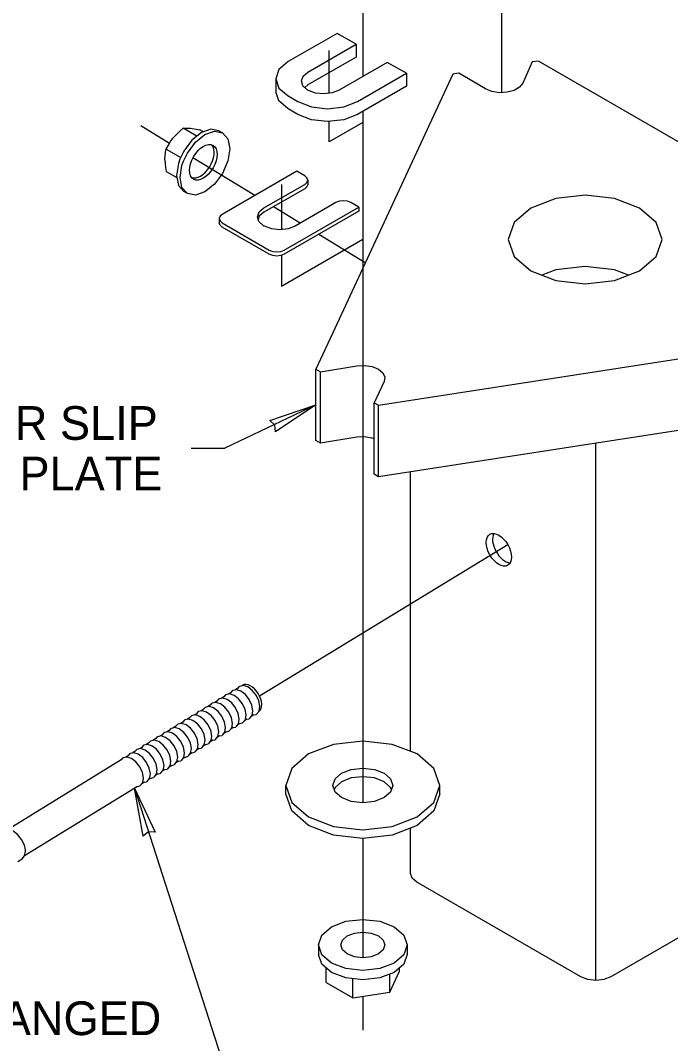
# Model space of a CAD drawing. Extents: x 99862 to 103151, y 99997 to 117076.
# Drawn here: x 100046.3 to 100354.6, y 103271 to 103756.6 of the extents above; entities that cross this region are included whole.
import ezdxf

# ---------------------------------------------------------------- set-up
doc = ezdxf.new("R2010")
doc.units = 0
for name, color, linetype in [('Default', 7, 'Continuous'), ('Level 13', 7, 'Continuous'), ('Level 15', 7, 'Continuous'), ('Level 20', 7, 'Continuous'), ('Level 4', 7, 'Continuous'), ('Level 5', 7, 'Continuous')]:
    doc.layers.add(name, color=color, linetype=linetype)

msp = doc.modelspace()

# ---------------------------------------------------------------- linework, layer by layer
at = {"layer": 'Default'}
for p, q in [((100208.71, 103891.51), (100208.71, 103729.96)), ((100274.4, 103781.42), (100274.4, 103722.3)), ((100182.62, 103732.04), (100205.47, 103745.24)), ((100192.69, 103722), (100192.69, 103742.22)), ((100206.13, 103718.06), (100229.34, 103731.46)), ((100208.71, 103713.42), (100208.71, 103385.26)), ((100192.69, 103698.9), (100192.69, 103708.63)), ((100208.71, 103708.14), (100192.69, 103698.9)), ((100161.8, 103667.56), (100181.12, 103678.72)), ((100170.11, 103678.77), (100170.11, 103657.3)), ((100208.71, 103652.54), (100170.11, 103630.25)), ((100170.11, 103645.05), (100170.11, 103630.25)), ((100195.4, 103610.36), (100186.43, 103591.03)), ((100186.43, 103591.03), (100188.55, 103589.81)), ((100214.01, 103575.11), (100216.13, 103573.89)), ((100319.2, 103300.86), (100319.2, 103555.95)), ((100231.31, 103409.63), (100231.31, 103542.35)), ((100153.76, 103424.92), (100154.81, 103425.16)), ((100155.09, 103425.33), (100154.81, 103425.16)), ((100157, 103426.92), (100158.06, 103427.15)), ((100158.33, 103427.32), (100158.06, 103427.15)), ((100147.27, 103420.93), (100148.33, 103421.17)), ((100148.6, 103421.33), (100148.33, 103421.17)), ((100150.51, 103422.93), (100151.57, 103423.16)), ((100151.84, 103423.33), (100151.57, 103423.16)), ((100138.86, 103415.35), (100138.59, 103415.18)), ((100140.78, 103416.94), (100141.84, 103417.17)), ((100142.11, 103417.34), (100141.84, 103417.17)), ((100144.02, 103418.93), (100145.08, 103419.17)), ((100145.35, 103419.34), (100145.08, 103419.17)), ((100131.04, 103410.95), (100132.1, 103411.19)), ((100132.37, 103411.35), (100132.1, 103411.19)), ((100134.29, 103412.95), (100135.35, 103413.18)), ((100135.62, 103413.35), (100135.35, 103413.18)), ((100137.53, 103414.94), (100138.59, 103415.18)), ((100124.55, 103406.96), (100125.61, 103407.19)), ((100125.88, 103407.36), (100125.61, 103407.19)), ((100127.8, 103408.95), (100128.86, 103409.19)), ((100129.13, 103409.36), (100128.86, 103409.19)), ((100114.82, 103400.97), (100115.88, 103401.21)), ((100116.15, 103401.37), (100115.88, 103401.21)), ((100118.06, 103402.97), (100119.12, 103403.2)), ((100119.39, 103403.37), (100119.12, 103403.2)), ((100121.31, 103404.96), (100122.37, 103405.2)), ((100122.64, 103405.37), (100122.37, 103405.2)), ((100108.33, 103396.98), (100109.39, 103397.21)), ((100109.66, 103397.38), (100109.39, 103397.21)), ((100111.58, 103398.97), (100112.63, 103399.21)), ((100112.91, 103399.38), (100112.63, 103399.21)), ((100101.84, 103392.99), (100102.9, 103393.22)), ((100103.17, 103393.39), (100102.9, 103393.22)), ((100105.09, 103394.98), (100106.14, 103395.22)), ((100106.42, 103395.39), (100106.14, 103395.22)), ((100208.71, 103368.33), (100208.71, 103311.71)), ((100187.71, 103317.77), (100187.71, 103313.28)), ((100191.28, 103299.97), (100191.28, 103306.93)), ((100221.46, 103295.3), (100221.46, 103303.9)), ((100204.04, 103292.6), (100204.04, 103301.69)), ((100208.71, 103293.32), (100208.71, 103277.32))]:
    msp.add_line(p, q, dxfattribs=at)
for points in [[(100205.47, 103745.24), (100196.46, 103750.44), (100173.25, 103737.04), (100168.91, 103733.3), (100167.39, 103728.88), (100167.39, 103722.75)], [(100205.47, 103745.24), (100205.47, 103739.11), (100182.62, 103725.92), (100181.19, 103724.7)], [(100229.34, 103731.46), (100220.32, 103736.66), (100197.47, 103723.47), (100194.15, 103722.17), (100190.23, 103721.69), (100186.29, 103722.09), (100182.89, 103723.32), (100182.62, 103723.47), (100182.35, 103723.62), (100180.24, 103725.58), (100179.54, 103727.86), (100179.54, 103727.86)], [(100469.45, 103600.93), (100469.45, 103634.82), (100291.97, 103737.29), (100289.07, 103736.84), (100284.56, 103726.78), (100283.04, 103724.85), (100280.45, 103723.34), (100277.12, 103722.44), (100273.45, 103722.26), (100269.9, 103722.82), (100266.91, 103724.05), (100254.29, 103731.46), (100251.4, 103731.01), (100195.4, 103610.36)], [(100229.34, 103731.46), (100229.34, 103725.33), (100206.13, 103711.93), (100199.64, 103709.43), (100191.99, 103708.55), (100184.33, 103709.43), (100177.85, 103711.93), (100173.25, 103714.59), (100168.91, 103718.33), (100167.39, 103722.75)], [(100179.54, 103727.86), (100180.38, 103730.12), (100182.62, 103732.04)], [(100167.39, 103728.88), (100168.91, 103724.46), (100173.25, 103720.71)], [(100173.25, 103720.71), (100177.85, 103718.06)], [(100177.85, 103718.06), (100184.33, 103715.55), (100191.99, 103714.68), (100199.64, 103715.55), (100206.13, 103718.06)], [(100182.59, 103680.76), (100182.21, 103681.87), (100181.12, 103682.8), (100177.41, 103684.95), (100142.05, 103664.53), (100140.97, 103663.6), (100140.59, 103662.49), (100140.59, 103660.45)], [(100182.59, 103680.76), (100182.59, 103678.72), (100182.21, 103677.62), (100181.12, 103676.68), (100161.8, 103665.52), (100159.56, 103663.61), (100159.07, 103662.27)], [(100181.12, 103678.72), (100182.21, 103679.66), (100182.59, 103680.76)], [(100350.65, 103652.62), (100347.87, 103660.69), (100339.96, 103667.52), (100328.12, 103672.09), (100314.15, 103673.7), (100300.19, 103672.09), (100288.34, 103667.52), (100280.43, 103660.69), (100277.65, 103652.62)], [(100206.76, 103668), (100206.76, 103665.96), (100171.4, 103645.55), (100169.78, 103644.92), (100167.86, 103644.7), (100165.95, 103644.92), (100164.33, 103645.55), (100142.05, 103658.41), (100140.97, 103659.35), (100140.59, 103660.45)], [(100206.76, 103668), (100203.04, 103670.15), (100201.42, 103670.77), (100199.51, 103670.99), (100197.59, 103670.77), (100195.97, 103670.15), (100176.65, 103658.99), (100173.33, 103657.7), (100169.41, 103657.22), (100165.47, 103657.62), (100162.07, 103658.84), (100161.8, 103658.99), (100161.54, 103659.14), (100159.42, 103661.11), (100158.73, 103663.39), (100158.73, 103663.39)], [(100164.33, 103647.59), (100165.95, 103646.97), (100167.86, 103646.75), (100169.78, 103646.97), (100171.4, 103647.59), (100206.76, 103668)], [(100158.73, 103663.39), (100159.56, 103665.65), (100161.8, 103667.56)], [(100140.59, 103662.49), (100140.97, 103661.39), (100142.05, 103660.45)], [(100142.05, 103660.45), (100164.33, 103647.59)], [(100277.65, 103652.62), (100280.43, 103644.56), (100288.34, 103637.72), (100300.19, 103633.15), (100314.15, 103631.55), (100328.12, 103633.15), (100339.96, 103637.72), (100347.87, 103644.56), (100350.65, 103652.62)], [(100334.67, 103635.68), (100328.12, 103638.21), (100314.15, 103639.81), (100300.19, 103638.21), (100293.63, 103635.68)], [(100216.13, 103540), (100216.13, 103573.89), (100458.58, 103611.4)], [(100214.01, 103558), (100213.12, 103558.37), (100209.56, 103558.91), (100205.9, 103558.7), (100188.55, 103555.93), (100186.43, 103557.15), (100186.43, 103591.03)], [(100188.55, 103555.93), (100188.55, 103589.81), (100205.9, 103592.59)], [(100205.9, 103592.59), (100209.56, 103592.79), (100213.12, 103592.25), (100216.13, 103591.03), (100218.24, 103589.29), (100219.17, 103587.24)], [(100219.17, 103587.24), (100219.17, 103587.24), (100218.82, 103585.13), (100214.01, 103575.11)], [(100459.36, 103579.18), (100458.58, 103577.51), (100216.13, 103540), (100214.01, 103541.23), (100214.01, 103575.11)], [(100158.33, 103427.32), (100159.48, 103428.72), (100159.83, 103430.91), (100159.34, 103433.55), (100158.08, 103436.25), (100156.24, 103438.59), (100154.1, 103440.22), (100151.99, 103440.89), (100150.22, 103440.5), (100149.95, 103440.33), (100149.27, 103439.49)], [(100148.6, 103421.33), (100149.74, 103422.73), (100150.1, 103424.92), (100149.61, 103427.56), (100148.35, 103430.26), (100146.51, 103432.61), (100144.37, 103434.24), (100142.25, 103434.91), (100140.49, 103434.51), (100140.22, 103434.34), (100139.53, 103433.51)], [(100151.84, 103423.33), (100152.99, 103424.73), (100153.34, 103426.91), (100152.85, 103429.56), (100151.59, 103432.26), (100149.75, 103434.6), (100147.61, 103436.23), (100145.5, 103436.9), (100143.74, 103436.51), (100143.46, 103436.34), (100142.78, 103435.5)], [(100155.09, 103425.33), (100156.23, 103426.72), (100156.59, 103428.91), (100156.1, 103431.56), (100154.84, 103434.26), (100153, 103436.6), (100150.86, 103438.23), (100148.74, 103438.9), (100146.98, 103438.5), (100146.71, 103438.34), (100146.02, 103437.5)], [(100142.11, 103417.34), (100143.25, 103418.74), (100143.61, 103420.93), (100143.12, 103423.57), (100141.86, 103426.27), (100140.02, 103428.61), (100137.88, 103430.24), (100135.77, 103430.91), (100134, 103430.52), (100133.73, 103430.35), (100133.04, 103429.51)], [(100145.35, 103419.34), (100146.5, 103420.73), (100146.86, 103422.92), (100146.36, 103425.57), (100145.1, 103428.27), (100143.26, 103430.61), (100141.12, 103432.24), (100139.01, 103432.91), (100137.25, 103432.52), (100136.97, 103432.35), (100136.29, 103431.51)], [(100135.62, 103413.35), (100136.77, 103414.75), (100137.12, 103416.93), (100136.63, 103419.58), (100135.37, 103422.28), (100133.53, 103424.62), (100131.39, 103426.25), (100129.28, 103426.92), (100127.51, 103426.53), (100127.24, 103426.36), (100126.55, 103425.52)], [(100138.86, 103415.35), (100140.01, 103416.74), (100140.37, 103418.93), (100139.88, 103421.58), (100138.61, 103424.27), (100136.77, 103426.62), (100134.63, 103428.25), (100132.52, 103428.92), (100130.76, 103428.52), (100130.48, 103428.36), (100129.8, 103427.52)], [(100125.88, 103407.36), (100127.03, 103408.76), (100127.39, 103410.95), (100126.9, 103413.59), (100125.64, 103416.29), (100123.79, 103418.63), (100121.65, 103420.26), (100119.54, 103420.93), (100117.78, 103420.54), (100117.51, 103420.37), (100116.82, 103419.53)], [(100129.13, 103409.36), (100130.28, 103410.75), (100130.63, 103412.94), (100130.14, 103415.59), (100128.88, 103418.29), (100127.04, 103420.63), (100124.9, 103422.26), (100122.79, 103422.93), (100121.02, 103422.54), (100120.75, 103422.37), (100120.06, 103421.53)], [(100132.37, 103411.35), (100133.52, 103412.75), (100133.88, 103414.94), (100133.39, 103417.58), (100132.12, 103420.28), (100130.28, 103422.63), (100128.14, 103424.26), (100126.03, 103424.93), (100124.27, 103424.53), (100124, 103424.36), (100123.31, 103423.53)], [(100119.39, 103403.37), (100120.54, 103404.77), (100120.9, 103406.95), (100120.41, 103409.6), (100119.15, 103412.3), (100117.3, 103414.64), (100115.17, 103416.27), (100113.05, 103416.94), (100111.29, 103416.55), (100111.02, 103416.38), (100110.33, 103415.54)], [(100122.64, 103405.37), (100123.79, 103406.76), (100124.14, 103408.95), (100123.65, 103411.6), (100122.39, 103414.29), (100120.55, 103416.64), (100118.41, 103418.27), (100116.3, 103418.94), (100114.53, 103418.54), (100114.26, 103418.38), (100113.57, 103417.54)], [(100109.66, 103397.38), (100110.81, 103398.78), (100111.16, 103400.97), (100110.67, 103403.61), (100109.41, 103406.31), (100107.57, 103408.65), (100105.43, 103410.28), (100103.32, 103410.95), (100101.55, 103410.56), (100101.28, 103410.39), (100100.59, 103409.55)], [(100112.91, 103399.38), (100114.05, 103400.77), (100114.41, 103402.96), (100113.92, 103405.61), (100112.66, 103408.31), (100110.82, 103410.65), (100108.68, 103412.28), (100106.56, 103412.95), (100104.8, 103412.56), (100104.53, 103412.39), (100103.84, 103411.55)], [(100116.15, 103401.37), (100117.3, 103402.77), (100117.65, 103404.96), (100117.16, 103407.6), (100115.9, 103410.3), (100114.06, 103412.65), (100111.92, 103414.28), (100109.81, 103414.95), (100108.04, 103414.55), (100107.77, 103414.38), (100107.08, 103413.55)], [(100245.21, 103389.41), (100245.21, 103393.49), (100242.43, 103401.55), (100234.52, 103408.39), (100222.67, 103412.96), (100208.71, 103414.56), (100194.74, 103412.96), (100182.9, 103408.39), (100174.98, 103401.55), (100172.21, 103393.49)], [(100103.17, 103393.39), (100104.32, 103394.79), (100104.67, 103396.97), (100104.18, 103399.62), (100102.92, 103402.32), (100101.08, 103404.66), (100098.94, 103406.29), (100096.83, 103406.96), (100095.06, 103406.57), (100094.79, 103406.4), (100094.1, 103405.56)], [(100106.42, 103395.39), (100107.56, 103396.78), (100107.92, 103398.97), (100107.43, 103401.62), (100106.17, 103404.31), (100104.33, 103406.66), (100102.19, 103408.29), (100100.07, 103408.96), (100098.31, 103408.56), (100098.04, 103408.4), (100097.35, 103407.56)], [(100194.46, 103393.49), (100195.54, 103396.64), (100198.63, 103399.31), (100203.25, 103401.09), (100208.71, 103401.72), (100214.16, 103401.09), (100218.78, 103399.31), (100221.87, 103396.64), (100222.96, 103393.49)], [(100222.25, 103391.45), (100221.87, 103392.55), (100218.78, 103395.22), (100214.16, 103397.01), (100208.71, 103397.63), (100203.25, 103397.01), (100198.63, 103395.22), (100195.54, 103392.55), (100195.16, 103391.45)], [(100245.21, 103389.41), (100242.43, 103381.34), (100234.52, 103374.5), (100222.67, 103369.94), (100208.71, 103368.33), (100194.74, 103369.94), (100182.9, 103374.5), (100174.98, 103381.34), (100172.21, 103389.41), (100172.21, 103393.49)], [(100172.21, 103393.49), (100174.98, 103385.42), (100182.9, 103378.59), (100194.74, 103374.02), (100208.71, 103372.41), (100222.67, 103374.02), (100234.52, 103378.59), (100242.43, 103385.42), (100245.21, 103393.49)], [(100222.96, 103393.49), (100222.96, 103393.49), (100221.87, 103390.34), (100218.78, 103387.67), (100214.16, 103385.89), (100208.71, 103385.26), (100203.25, 103385.89), (100198.63, 103387.67), (100195.54, 103390.34), (100194.46, 103393.49)], [(100407.09, 103351.6), (100406.33, 103349.4), (100404.16, 103347.52), (100326.27, 103302.55), (100323.03, 103301.3), (100319.2, 103300.86), (100315.37, 103301.3), (100312.13, 103302.55), (100234.24, 103347.52), (100232.07, 103349.4), (100231.31, 103351.6), (100231.31, 103373.27)], [(100187.71, 103317.77), (100189.31, 103322.41), (100193.86, 103326.34), (100200.67, 103328.97), (100208.71, 103329.89), (100216.74, 103328.97), (100223.56, 103326.34), (100228.11, 103322.41), (100229.71, 103317.77), (100229.71, 103313.28), (100228.11, 103308.64), (100223.56, 103304.7), (100216.74, 103302.08), (100208.71, 103301.15), (100200.67, 103302.08), (100193.86, 103304.7), (100189.31, 103308.64), (100187.71, 103313.28)], [(100198.21, 103317.77), (100199.01, 103320.09), (100201.28, 103322.05), (100204.69, 103323.37), (100208.71, 103323.83), (100212.72, 103323.37), (100216.13, 103322.05), (100218.41, 103320.09), (100219.21, 103317.77)], [(100229.71, 103317.77), (100228.11, 103313.13), (100223.56, 103309.19), (100216.74, 103306.57), (100208.71, 103305.64), (100200.67, 103306.57), (100193.86, 103309.19), (100189.31, 103313.13), (100187.71, 103317.77)], [(100219.21, 103317.77), (100218.41, 103315.45), (100216.13, 103313.48), (100212.72, 103312.17), (100208.71, 103311.71), (100204.69, 103312.17), (100201.28, 103313.48), (100199.01, 103315.45), (100198.21, 103317.77), (100198.21, 103317.77)], [(100191.28, 103299.97), (100204.04, 103292.6), (100221.46, 103295.3), (100226.13, 103305.36), (100226.13, 103306.93)]]:
    msp.add_lwpolyline(points, dxfattribs=at)
at = {"layer": 'Level 13'}
for p, q in [((100129.95, 103701.64), (100123.46, 103705.39)), ((100129.95, 103701.64), (100123.46, 103705.39)), ((100133.07, 103703.72), (100131.42, 103704.67)), ((100133.07, 103703.72), (100131.42, 103704.67)), ((100115.5, 103695.48), (100122.32, 103691.55)), ((100115.5, 103695.48), (100122.32, 103691.55))]:
    msp.add_line(p, q, dxfattribs=at)
for points in [[(100114.79, 103690.4), (100114.79, 103690.78), (100114.8, 103690.95), (100115.13, 103693.79), (100115.18, 103694.21), (100115.5, 103695.48), (100116.53, 103697.36), (100117.46, 103699.03), (100118.59, 103700.61), (100118.96, 103701.08), (100119.05, 103701.18), (100121.7, 103703.87), (100122.05, 103704.21), (100123.46, 103705.39), (100124.11, 103705.46), (100124.51, 103705.47), (100126.11, 103705.49), (100126.56, 103705.45), (100126.9, 103705.42), (100127.8, 103705.32), (100129.79, 103704.97), (100131.42, 103704.67)], [(100114.79, 103690.4), (100114.79, 103690.78), (100114.8, 103690.95), (100115.13, 103693.79), (100115.18, 103694.21), (100115.5, 103695.48), (100116.53, 103697.36), (100117.46, 103699.03), (100118.59, 103700.61), (100118.96, 103701.08), (100119.05, 103701.18), (100121.7, 103703.87), (100122.05, 103704.21), (100123.46, 103705.39), (100124.11, 103705.46), (100124.51, 103705.47), (100126.11, 103705.49), (100126.56, 103705.45), (100126.9, 103705.42), (100127.8, 103705.32), (100129.79, 103704.97), (100131.42, 103704.67)], [(100142.16, 103703.24), (100140.46, 103704.22), (100136.64, 103704.96), (100132.12, 103703.39), (100127.61, 103699.75), (100123.78, 103694.59), (100121.91, 103690.68), (100121.23, 103688.69), (100120.33, 103682.96), (100121.23, 103678.27), (100123.78, 103675.33)], [(100125.48, 103674.35), (100122.92, 103677.29), (100122.02, 103681.98), (100122.92, 103687.72), (100123.6, 103689.71), (100125.48, 103693.61), (100129.3, 103698.77), (100133.82, 103702.41), (100138.33, 103703.98), (100142.16, 103703.24)], [(100142.16, 103703.24), (100144.71, 103700.3), (100145.61, 103695.6), (100144.71, 103689.87), (100142.16, 103683.98), (100138.33, 103678.82), (100133.82, 103675.18), (100129.3, 103673.61), (100125.48, 103674.35), (100123.78, 103675.33)], [(100114.79, 103690.4), (100114.89, 103688.64), (100115.18, 103686.83), (100115.5, 103684.87), (100120.52, 103681.97)], [(100114.79, 103690.4), (100114.89, 103688.64), (100115.18, 103686.83), (100115.5, 103684.87), (100120.52, 103681.97)]]:
    msp.add_lwpolyline(points, dxfattribs=at)
msp.add_ellipse((100133.03, 103689.22), major_axis=(-4.63, -8.02), ratio=0.57735, dxfattribs=at)
for centre, major_axis, start_param, end_param in [((100131.68, 103690.25), (-4.63, -8.02), 0.083455, 2.907882), ((100155.52, 103434.79), (-3.82, 6.2), 3.161411, 6.283198)]:
    msp.add_ellipse(centre, major_axis=major_axis, ratio=0.57735, start_param=start_param, end_param=end_param, dxfattribs=at)
at = {"layer": 'Level 15'}
for p, q in [((100117, 103698.21), (100103.34, 103706.54)), ((100157.56, 103673.48), (100128.14, 103691.42)), ((100179.05, 103660.38), (100166.32, 103668.14)), ((100209.89, 103641.57), (100187.82, 103655.03)), ((100186.43, 103574.09), (100143.3, 103553.5)), ((100127.3, 103553.5), (100143.3, 103553.5)), ((100159.63, 103435.99), (100277.4, 103507.81)), ((100100.43, 103392.12), (100143.3, 103258.96))]:
    msp.add_line(p, q, dxfattribs=at)
for points in [[(100186.43, 103574.09), (100167.28, 103561.32), (100166.9, 103564.47), (100164.64, 103566.68)], [(100100.43, 103392.12), (100110.26, 103371.3), (100107.1, 103371.39), (100104.58, 103369.47)]]:
    msp.add_lwpolyline(points, close=True, dxfattribs=at)
at = {"layer": 'Level 4'}
msp.add_ellipse((100273.19, 103505.3), major_axis=(4.25, -7.36), ratio=0.57735, dxfattribs=at)
msp.add_ellipse((100276.22, 103506.8), major_axis=(4.25, -7.36), ratio=0.57735, start_param=3.454767, end_param=5.89408, dxfattribs=at)
at = {"layer": 'Level 5'}
for p, q in [((100151.7, 103441), (100151.28, 103440.74)), ((100142.78, 103435.5), (100141.55, 103434.75)), ((100146.02, 103437.5), (100144.79, 103436.74)), ((100149.27, 103439.49), (100148.04, 103438.74)), ((100136.29, 103431.51), (100135.06, 103430.76)), ((100139.53, 103433.51), (100138.3, 103432.75)), ((100126.55, 103425.52), (100125.33, 103424.77)), ((100129.8, 103427.52), (100128.57, 103426.76)), ((100133.04, 103429.51), (100131.81, 103428.76)), ((100120.06, 103421.53), (100118.84, 103420.78)), ((100123.31, 103423.53), (100122.08, 103422.77)), ((100110.33, 103415.54), (100109.1, 103414.79)), ((100113.57, 103417.54), (100112.35, 103416.78)), ((100116.82, 103419.53), (100115.59, 103418.78)), ((100103.84, 103411.55), (100102.61, 103410.8)), ((100107.08, 103413.55), (100105.86, 103412.79)), ((100097.35, 103407.56), (100096.12, 103406.8)), ((100100.59, 103409.55), (100099.37, 103408.8)), ((100094.1, 103405.56), (100040.55, 103372.62))]:
    msp.add_line(p, q, dxfattribs=at)
for points in [[(100157, 103426.92), (100155.77, 103426.16)], [(100147.27, 103420.93), (100146.04, 103420.18)], [(100150.51, 103422.93), (100149.29, 103422.17)], [(100153.76, 103424.92), (100152.53, 103424.17)], [(100140.78, 103416.94), (100139.55, 103416.18)], [(100144.02, 103418.93), (100142.8, 103418.18)], [(100131.04, 103410.95), (100129.82, 103410.2)], [(100134.29, 103412.95), (100133.06, 103412.19)], [(100137.53, 103414.94), (100136.31, 103414.19)], [(100124.55, 103406.96), (100123.33, 103406.2)], [(100127.8, 103408.95), (100126.57, 103408.2)], [(100114.82, 103400.97), (100113.59, 103400.22)], [(100118.06, 103402.97), (100116.84, 103402.21)], [(100121.31, 103404.96), (100120.08, 103404.21)], [(100108.33, 103396.98), (100107.1, 103396.22)], [(100111.58, 103398.97), (100110.35, 103398.22)], [(100101.84, 103392.99), (100048.29, 103360.04)], [(100105.09, 103394.98), (100103.86, 103394.23)], [(100045.01, 103357.32), (100047.12, 103358.62), (100048.31, 103360.06), (100048.67, 103362.32), (100048.64, 103362.88), (100048.17, 103365.05), (100046.87, 103367.84), (100044.97, 103370.25), (100042.76, 103371.94), (100040.58, 103372.63), (100038.76, 103372.22), (100036.59, 103370.89)]]:
    msp.add_lwpolyline(points, dxfattribs=at)

# ---------------------------------------------------------------- texts
at = {"layer": 'Level 20'}
for s, p in [('LOWER SLIP', (99980.66, 103557.5)), ('PLATE', (100045.86, 103533.5)), ('FLANGED ', (100012.05, 103274.96))]:
    msp.add_text(s, height=16, dxfattribs=at).set_placement(p)

doc.saveas('drawing.dxf')
